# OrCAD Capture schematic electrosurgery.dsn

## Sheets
1 DAC904 Output Translation: size A; title: Electrosurgery - DAC904 Output Translation; rev: 1
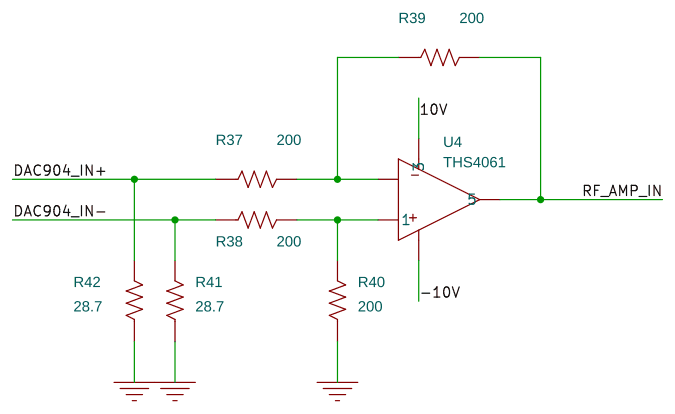
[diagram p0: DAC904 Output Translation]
2 Current and Voltage Sensing: size A; title: Electrosurgery - Current and Voltage Sensing
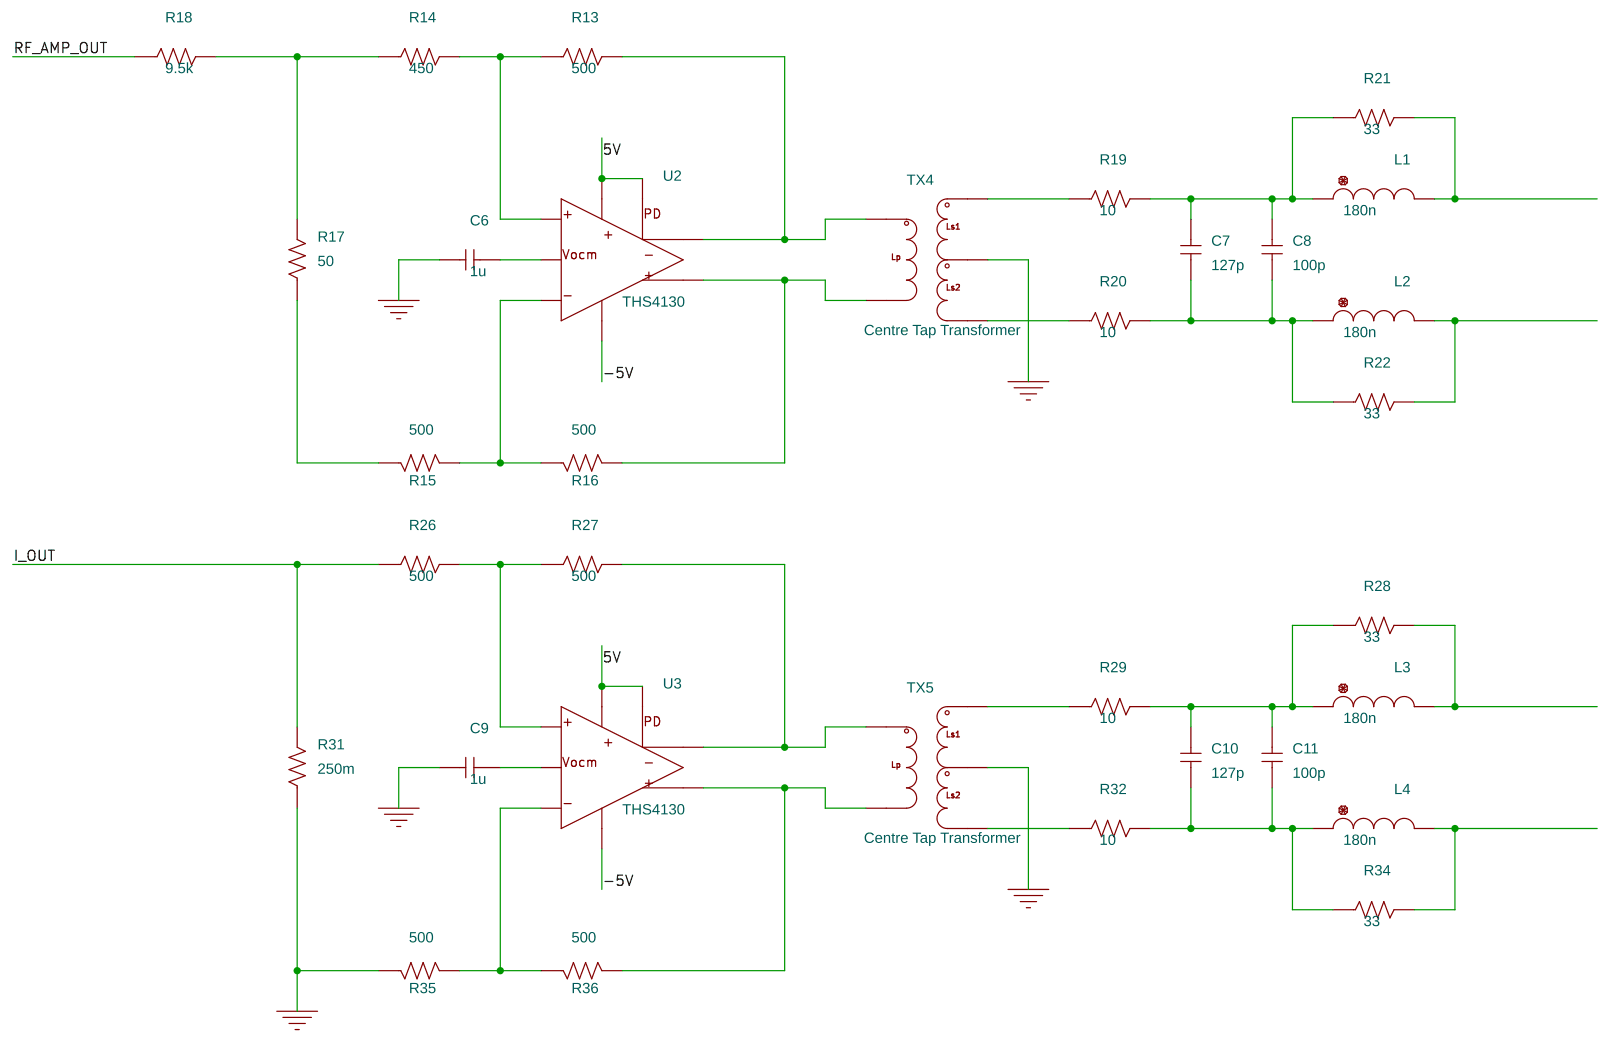
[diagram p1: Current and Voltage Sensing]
3 Sources: size A; title: Electrosurgery - Sources
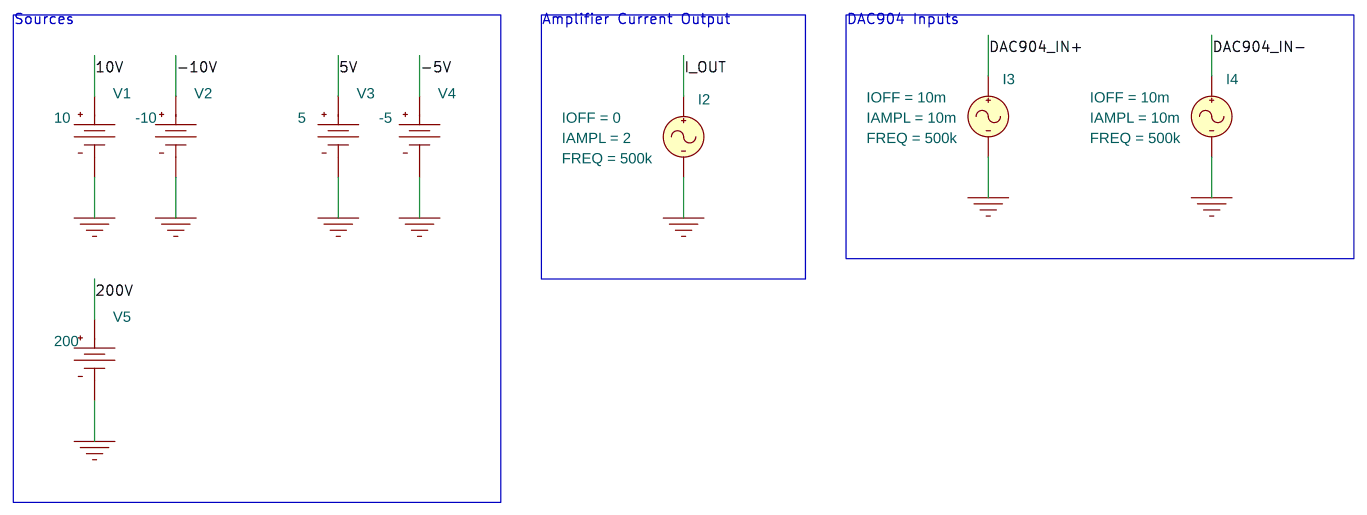
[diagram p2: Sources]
4 RF Amplifier: size A; title: Electrosurgery - RF Amplifier
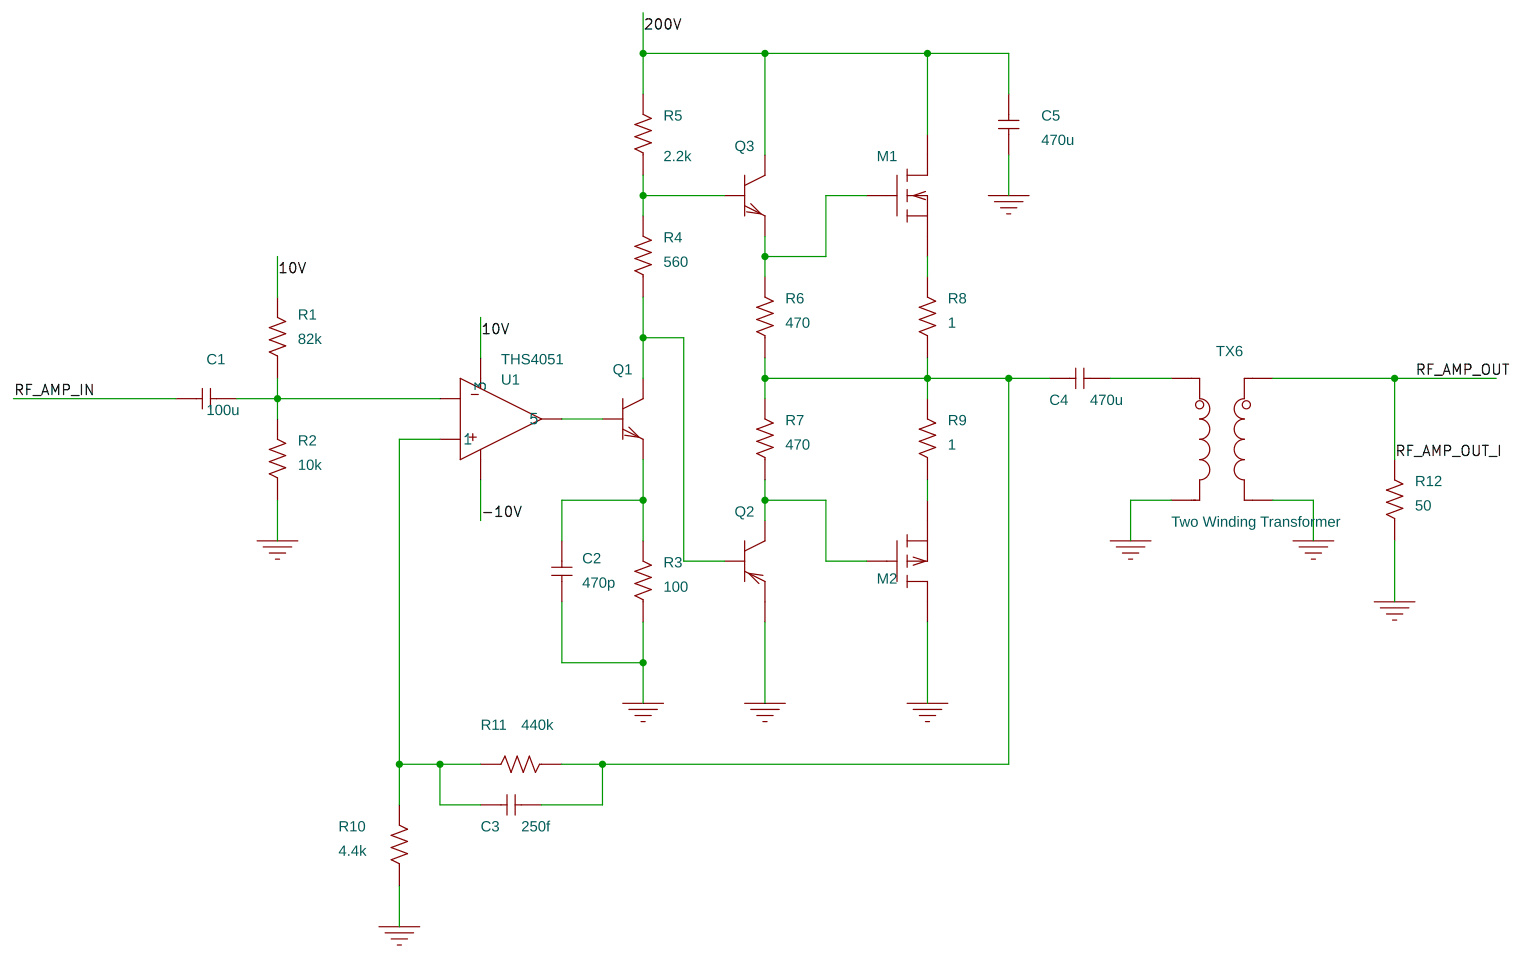
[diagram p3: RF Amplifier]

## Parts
sheet Current and Voltage Sensing
C6  1u  [cap196]
C7  127p  [cap196]
C8  100p  [cap196]
C9  1u  [cap196]
C10  127p  [cap196]
C11  100p  [cap196]
L1  180n  [DISC350x175LS200x100034]
L2  180n  [DISC350x175LS200x100034]
L3  180n  [DISC350x175LS200x100034]
L4  180n  [DISC350x175LS200x100034]
R13  500  [AXRC05]
R14  450  [AXRC05]
R15  500  [AXRC05]
R16  500  [AXRC05]
R17  50  [AXRC05]
R18  9.5k  [AXRC05]
R19  10  [AXRC05]
R20  10  [AXRC05]
R21  33  [AXRC05]
R22  33  [AXRC05]
R26  500  [AXRC05]
R27  500  [AXRC05]
R28  33  [AXRC05]
R29  10  [AXRC05]
R31  250m  [AXRC05]
R32  10  [AXRC05]
R34  33  [AXRC05]
R35  500  [AXRC05]
R36  500  [AXRC05]
TX4  Centre Tap Transformer
TX5  Centre Tap Transformer
U2  THS4130
U3  THS4130
sheet DAC904 Output Translation
R37  200  [AXRC05]
R38  200  [AXRC05]
R39  200  [AXRC05]
R40  200  [AXRC05]
R41  28.7  [AXRC05]
R42  28.7  [AXRC05]
U4  THS4061
sheet RF Amplifier
C1  100u  [cap196]
C2  470p  [cap196]
C3  250f  [cap196]
C4  470u  [cap196]
C5  470u  [cap196]
M1  power_Mbreakn
M2  POWER_PMOS_P
Q1  QbreakN
Q2  QbreakP
Q3  QbreakN
R1  82k  [AXRC05]
R2  10k  [AXRC05]
R3  100  [AXRC05]
R4  560  [AXRC05]
R5  2.2k  [AXRC05]
R6  470  [AXRC05]
R7  470  [AXRC05]
R8  1  [AXRC05]
R9  1  [AXRC05]
R10  4.4k  [AXRC05]
R11  440k  [AXRC05]
R12  50  [AXRC05]
TX6  Two Winding Transformer
U1  THS4051
sheet Sources
I2  ISIN
I3  ISIN
I4  ISIN
V1  VDC
V2  VDC
V3  VDC
V4  VDC
V5  VDC

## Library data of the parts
C1-C11 = C
L1-L4 = L
R1-R22 R26-R29 R31 R32 R34-R42 = R
TX4 = CETAPS: AppProp: modelname=CETAPS_Model,LP1=1m,RP1=10m,Rs1=10m,N=1,LI=100n
TX5 = CETAPS: AppProp: modelname=CETAPS_Model,LP1=1m,RP1=10m,Rs1=10m,N=2,LI=100n
U2 = THS4130_1: Testbenches: [{"TestbenchDisplayName": "THS4130 Simulation Model", "TestbenchURL": "https://software-dl.ti.com/pspice/esd/models/THS4130_V1.0.zip", "TestbenchOpj": "THS4130.opj"}]; Version: 1; productURL: http://www.ti.com/document-viewer/THS4130/datasheet/
U3 = THS4130: Testbenches: [{"TestbenchDisplayName": "THS4130 Simulation Model", "TestbenchURL": "https://software-dl.ti.com/pspice/esd/models/THS4130_V1.0.zip", "TestbenchOpj": "THS4130.opj"}]; Version: 1; productURL: http://www.ti.com/document-viewer/THS4130/datasheet/
U4 = THS4061: Testbenches: []; Version: 1; productURL: http://www.ti.com/product/THS4061
M1 = power_Mbreakn
M2 = POWER_PMOS_P
Q1 Q3 = QbreakN
Q2 = QbreakP
TX6 = ST: AppProp: modelname=ST_Model,LP1=1m,RP1=10m,Rs1=10m,N=2,LI=100n
U1 = THS4051: Testbenches: []; Version: 1; productURL: http://www.ti.com/product/THS4051
I2 = ISIN: AC: 0; AppProp: Sine$Current$0$-1; DC: 0; FREQ: 500k; IAMPL: 2; IOFF: 0
I3 = ISIN: AC: 0; AppProp: Sine$Current$0$-1; DC: 0; FREQ: 500k; IAMPL: 10m; IOFF: 10m
I4 = ISIN: AC: 0; AppProp: Sine$Current$0$-1; DC: 0; FREQ: 500k; IAMPL: 10m; IOFF: 10m; PHASE: 180
V1 = VDC: AppProp: DC$Voltage$0$-1; DC: 10
V2 = VDC: AppProp: DC$Voltage$0$-1; DC: -10
V3 = VDC: AppProp: DC$Voltage$0$-1; DC: 5
V4 = VDC: AppProp: DC$Voltage$0$-1; DC: -5
V5 = VDC: AppProp: DC$Voltage$0$-1; DC: 200

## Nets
5V: U2.3 U2.7 U3.3 U3.7
5V (page Sources): V3.0(+)
10V: U4.7(3)
10V (page RF Amplifier): R1.2 U1.7(3)
10V (page Sources): V1.0(+)
200V: C5.2 M1.2(d) Q3.1(c) R5.2
200V (page Sources): V5.0(+)
-5V: U2.6 U3.6
-5V (page Sources): V4.0(+)
-10V: U4.4
-10V (page RF Amplifier): U1.4
-10V (page Sources): V2.0(+)
0: C2.1 C5.1 C6.1 C9.1 I2.2(-) I3.2(-) I4.2(-) M2.2(d) Q2.2(e) R2.1 R3.1 R10.1 R12.1 R31.1 R35.1 R40.1 R41.1 R42.1 TX4.3(5) TX5.3(5) TX6.2 TX6.4 V1.1(-) V2.1(-) V3.1(-) V4.1(-) V5.1(-)
DAC904_IN+: R37.1 R42.2
DAC904_IN+ (page Sources): I3.1(+)
DAC904_IN-: R38.1 R41.2
DAC904_IN- (page Sources): I4.1(+)
I_OUT: R26.1 R31.2
I_OUT (page Sources): I2.1(+)
RF_AMP_IN: R39.2 U4.6(5)
RF_AMP_IN (page RF Amplifier): C1.1
RF_AMP_OUT: R18.1
RF_AMP_OUT (page RF Amplifier): R12.2 TX6.3
N03385: Q3.0(b) R4.2 R5.1
N03413: M1.1(g) Q3.2(e) R6.2
N03463: M1.0(s) R8.2
N03467: Q1.1(c) Q2.0(b) R4.1
N03537: C3.2 C4.1 R6.1 R7.2 R8.1 R9.2 R11.1
N03577: C1.2 R1.1 R2.2 U1.2
N03691: Q1.0(b) U1.6(5)
N03759: C3.1 R10.2 R11.2 U1.3(1)
N03767: C2.2 Q1.2(e) R3.2
N03777: M2.0(g) Q2.1(c) R7.1
N03781: M2.1(s) R9.1
N08049: C4.2 TX6.1
N10084: R14.1 R17.2 R18.2
N10096: R13.1 R14.2 U2.8
N10108: R13.2 TX4.0(1) U2.5
N10132: C7.2 C8.2 L1.1 R19.2 R21.1
N10140: L1.2 R21.2
N10254: R19.1 TX4.2(4)
N10386: C6.2 U2.2
N10398: R16.2 TX4.1(3) U2.4
N10414: C7.1 C8.1 L2.1 R20.2 R22.1
N10438: R15.1 R17.1
N10450: R15.2 R16.1 U2.1
N10494: R20.1 TX4.4(6)
N10518: L2.2 R22.2
N10666: R26.2 R27.1 U3.8
N10678: R27.2 TX5.0(1) U3.5
N10702: C10.2 C11.2 L3.1 R28.1 R29.2
N10710: L3.2 R28.2
N10824: R29.1 TX5.2(4)
N10956: C9.2 U3.2
N10968: R36.2 TX5.1(3) U3.4
N10984: C10.1 C11.1 L4.1 R32.2 R34.1
N11020: R35.2 R36.1 U3.1
N11064: R32.1 TX5.4(6)
N11088: L4.2 R34.2
N13695: R37.2 R39.1 U4.2
N13699: R38.2 R40.2 U4.3(1)

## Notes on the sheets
sheet 3
- Sources
- Amplifier Current Output
- DAC904 Inputs
